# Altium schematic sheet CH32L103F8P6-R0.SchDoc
size 304 x 254 mm
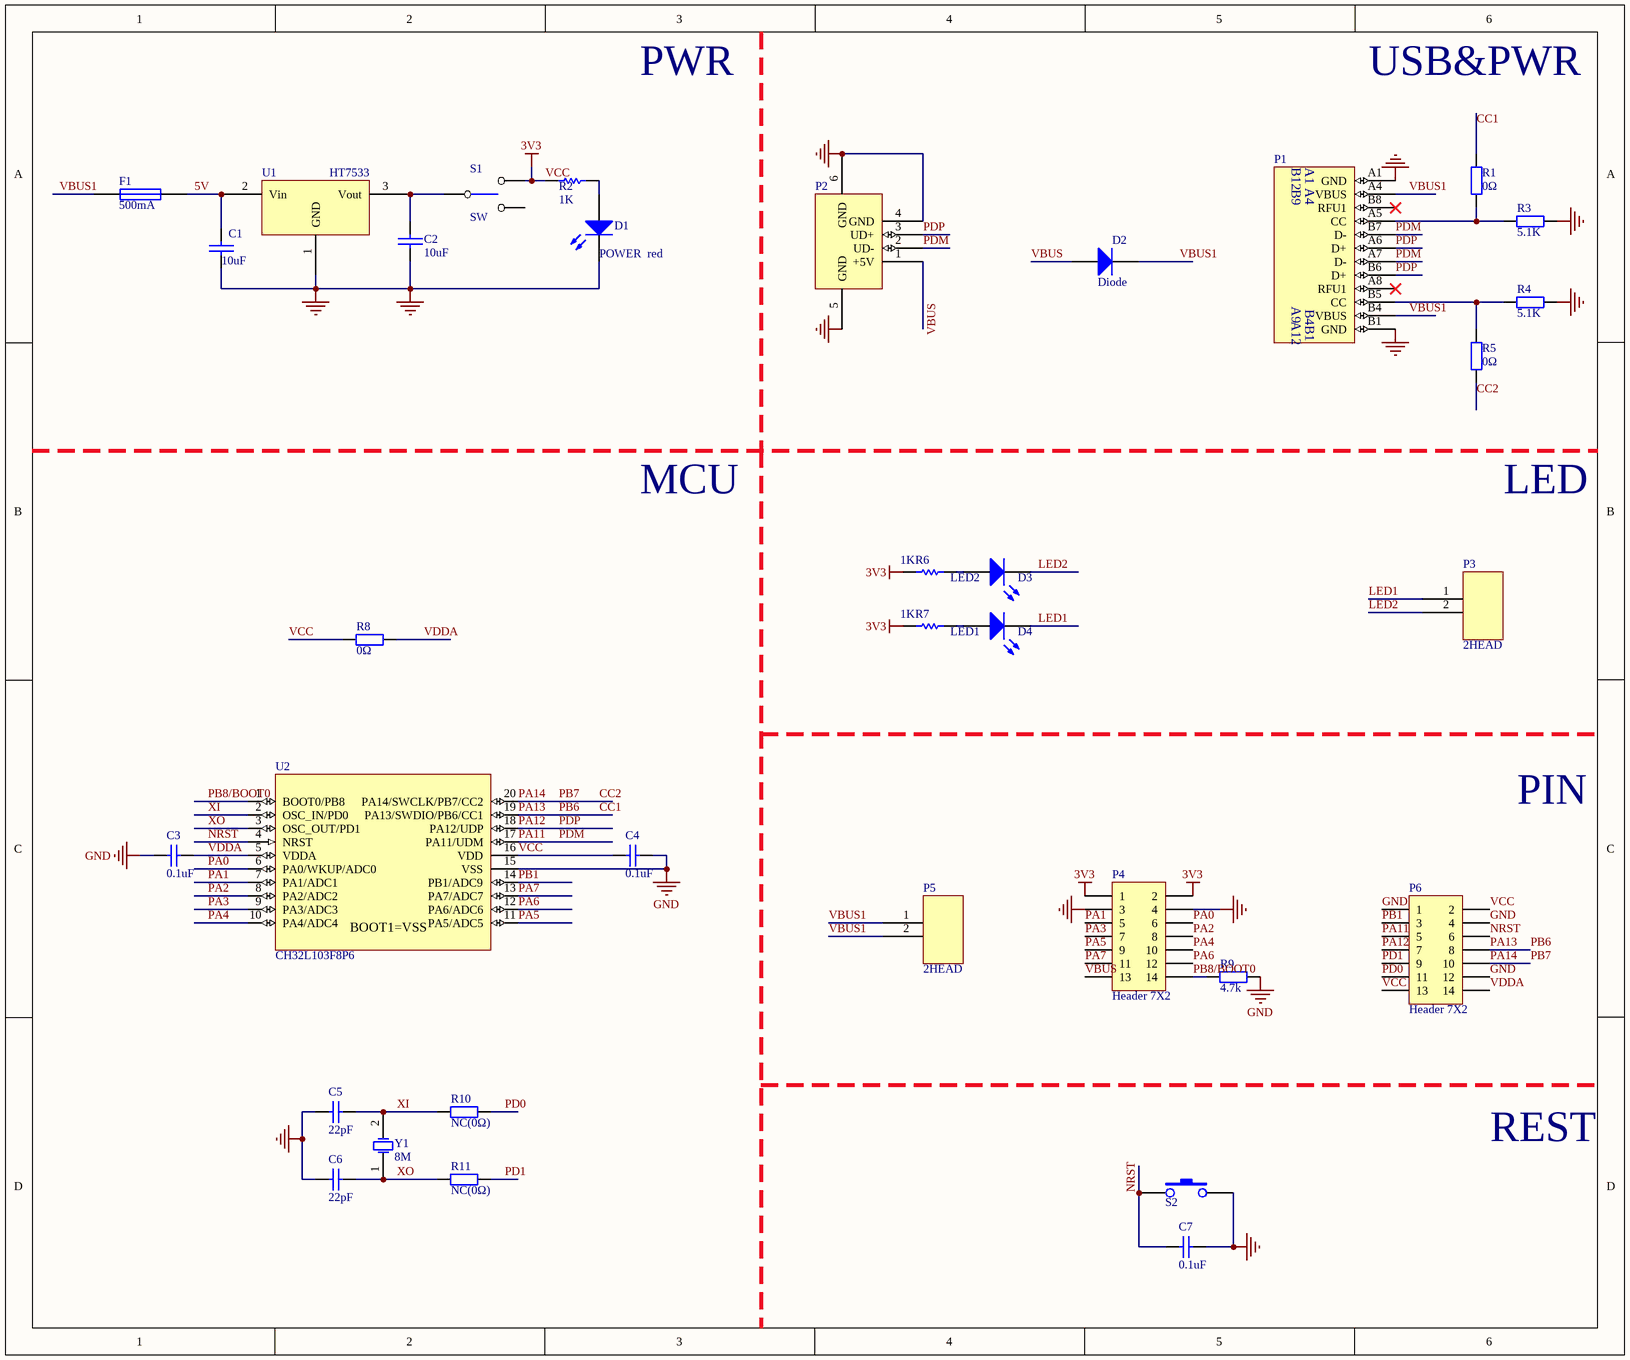
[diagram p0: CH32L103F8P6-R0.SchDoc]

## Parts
C1  10uF  [0603_C]
C2  10uF  [0603_C]
C3  0.1uF  [0603_C]
C4  0.1uF  [0603_C]
C5  22pF  [0603_C]
C6  22pF  [0603_C]
C7  0.1uF  [0603_C]
D1  POWER  red  [0603+]
D2  Diode  [SOD-123]
D3  LED2  [0603+]
D4  LED1  [0603+]
F1  500mA  [0603]
P1  TYPE-C  [TYPE-C-Receptacle-2.0]  (value not drawn)
P2  USB_A  [USBAF]  (value not drawn)
P3  2HEAD  [SIP2-2.54mm]
P4  Header 7X2  [IDC14-2.54mm]
P5  2HEAD  [SIP2-2.54mm]
P6  Header 7X2  [IDC14-2.54mm]
R1  0Ω  [0603]
R2  1K  [0603]
R3  5.1K  [0603]
R4  5.1K  [0603]
R5  0Ω  [0603]
R6  1K  [0603]
R7  1K  [0603]
R8  0Ω  [0603]
R9  4.7k  [0603]
R10  NC(0Ω)  [0603]
R11  NC(0Ω)  [0603]
S1  SW  [SW1]
S2  KEY  [贴片按键]  (value not drawn)
U1  HT7533  [SOT-89]
U2  CH32L103F8P6  [TSSOP20]
Y1  8M  [XT_AT49]

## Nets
GND: C1.2 C2.2 C3.2 C4.2 C5.1 C6.1 C7.1 D1.2(K) P1.A1(GND) P1.B1(GND) P2.4(GND) P2.5(GND) P2.6(GND) P4.3 P4.4 P6.1 P6.4 P6.12 R3.2 R4.2 R9.2 S2.3 U1.1(GND) U2.15(VSS)
VCC: C4.1 P4.1 P4.2 P6.2 P6.13 R2.2 R6.1 R7.1 R8.1 S1.3 U2.16(VDD)  [also labelled 3V3]
5V: C1.1 F1.2 U1.2(Vin)
CC1: P6.8 R1.2 U2.19(PA13/SWDIO/PB6/CC1)  [also labelled PA13, PB6]
CC2: P6.10 R5.1 U2.20(PA14/SWCLK/PB7/CC2)  [also labelled PA14, PB7]
LED1: D4.2(K) P3.1
LED2: D3.2(K) P3.2
NRST: C7.2 P6.6 S2.1 U2.4(NRST)
PA0: P4.6 U2.6(PA0/WKUP/ADC0)
PA1: P4.5 U2.7(PA1/ADC1)
PA2: P4.8 U2.8(PA2/ADC2)
PA3: P4.7 U2.9(PA3/ADC3)
PA4: P4.10 U2.10(PA4/ADC4)
PA5: P4.9 U2.11(PA5/ADC5)
PA6: P4.12 U2.12(PA6/ADC6)
PA7: P4.11 U2.13(PA7/ADC7)
PA11: P1.A7(D-) P1.B7(D-) P2.2(UD-) P6.5 U2.17(PA11/UDM)  [also labelled PDM]
PA12: P1.A6(D+) P1.B6(D+) P2.3(UD+) P6.7 U2.18(PA12/UDP)  [also labelled PDP]
PB1: P6.3 U2.14(PB1/ADC9)
PB8/BOOT0: P4.14 R9.1 U2.1(BOOT0/PB8)
PD0: P6.11 R10.1
PD1: P6.9 R11.1
VBUS: D2.1(A) P2.1(+5V) P4.13
VBUS1: D2.2(K) F1.1 P1.A4(VBUS) P1.B4(VBUS) P5.1 P5.2
VDDA: C3.1 P6.14 R8.2 U2.5(VDDA)
XI: C5.2 R10.2 U2.2(OSC_IN/PD0) Y1.2(OSC2)
XO: C6.2 R11.2 U2.3(OSC_OUT/PD1) Y1.1(OSC1)
NetC2_1: C2.1 S1.1 U1.3(Vout)
NetD1_1: D1.1(A) R2.1
NetD3_1: D3.1(A) R6.2
NetD4_1: D4.1(A) R7.2
NetP1_A5: P1.A5(CC) R1.1 R3.1
NetP1_B5: P1.B5(CC) R4.1 R5.2

Not connected (* = marked no-connect by the designer): P1 A8(RFU1)* B8(RFU1)*; S1 2

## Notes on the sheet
- PWR
- USB&PWR
- MCU
- LED
- PIN
- REST

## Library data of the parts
C1 C2 = CAP: Capacitor
C3 C4 = Cap: Capacitor; Value: 15pF
C5-C7 = Cap: Capacitor
D1 D3 D4 = LED0: Typical INFRARED GaAs LED
D2 = Diode: Default Diode
F1 = FUSE1: Fuse
P1 = TYPE-C1
P2 = USB: USB Port
P4 P6 = Header 7X2: Header, 7-Pin, Dual row
R1 R3-R5 R8-R11 = Res2: Resistor
R2 R6 R7 = Res Semi: Semiconductor Resistor
U1 = 1117-3.3V
U2 = CH32L103F8P6: RISC-V LMD-MCU, 96MHz, USB, Type-C/PD, CAN, OPA, lower power
Y1 = XTAL: Crystal Oscillator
